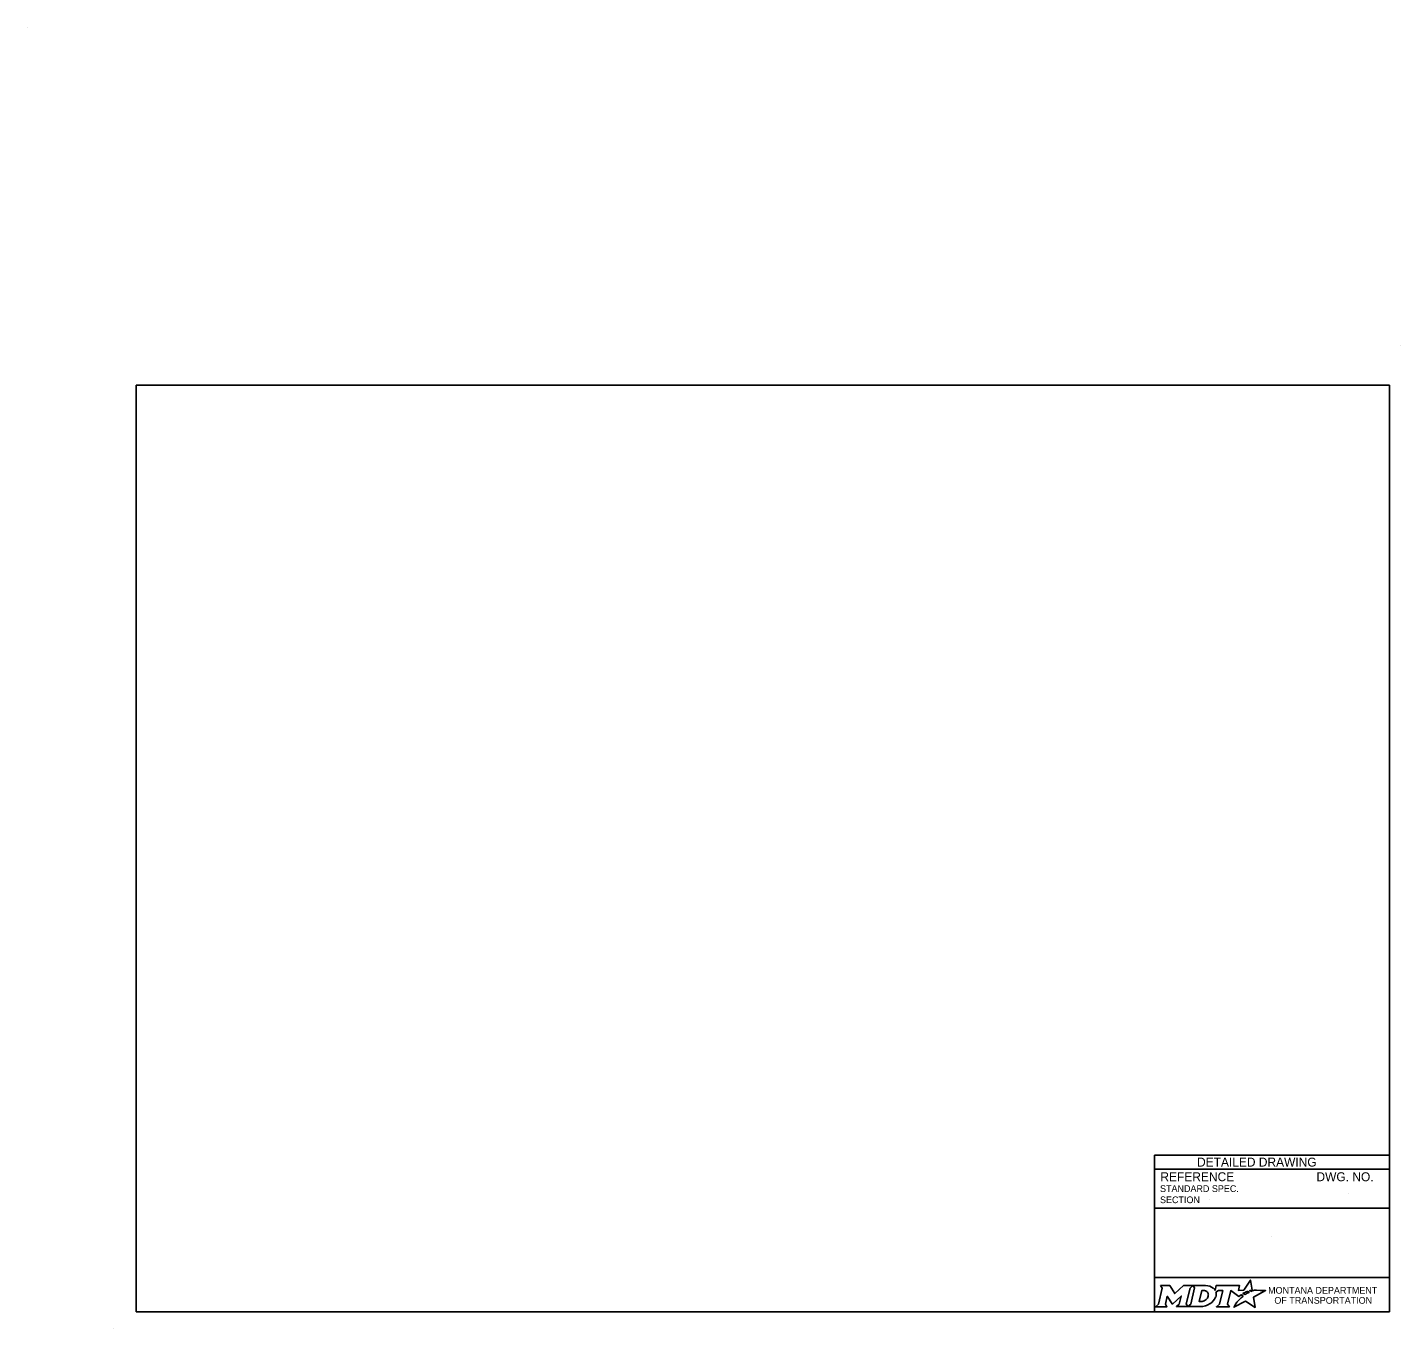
# Model space of a CAD drawing. Extents: x 49991.4 to 50021, y 49987.6 to 50011.4.
# Drawn here: x 50008.76 to 50021.04, y 49999.74 to 50011.36 of the extents above; entities that cross this region are included whole.
import ezdxf

# ---------------------------------------------------------------- set-up
doc = ezdxf.new("R2010")
doc.units = 0
for name, color, linetype in [('Default', 7, 'Continuous'), ('Level 1', 7, 'Continuous'), ('Level 4', 7, 'Continuous')]:
    doc.layers.add(name, color=color, linetype=linetype)

msp = doc.modelspace()

# ---------------------------------------------------------------- linework, layer by layer
at = {"layer": 'Default'}
for points in [[(50018.893, 50000.121), (50018.907, 50000.097), (50018.874, 49999.954), (50018.848, 49999.931), (50018.95, 49999.931), (50018.936, 49999.954), (50018.952, 50000.024), (50018.996, 49999.955), (50019.002, 49999.955), (50019.077, 50000.025), (50019.06, 49999.954), (50019.035, 49999.932), (50019.137, 49999.932), (50019.123, 49999.955), (50019.156, 50000.097)], [(50019.156, 50000.097), (50019.182, 50000.121), (50019.099, 50000.121), (50019.02, 50000.048), (50018.975, 50000.12), (50018.893, 50000.121)], [(50019.295, 50000.121), (50019.182, 50000.121), (50019.196, 50000.098), (50019.163, 49999.954), (50019.137, 49999.932), (50019.248, 49999.932)], [(50019.7, 50000.068), (50019.69, 50000.074), (50019.702, 50000.076), (50019.713, 50000.078), (50019.696, 50000.168), (50019.636, 50000.077), (50019.589, 50000.076), (50019.599, 50000.12), (50019.39, 50000.121), (50019.38, 50000.078), (50019.374, 50000.086)], [(50019.319, 50000.034), (50019.318, 50000.026), (50019.315, 50000.017), (50019.311, 50000.008), (50019.305, 50000.001), (50019.299, 49999.994), (50019.291, 49999.988), (50019.282, 49999.983), (50019.273, 49999.979), (50019.264, 49999.977), (50019.255, 49999.976), (50019.239, 49999.976), (50019.263, 50000.076), (50019.279, 50000.076), (50019.286, 50000.075), (50019.294, 50000.073), (50019.301, 50000.07), (50019.307, 50000.066), (50019.311, 50000.061), (50019.315, 50000.055), (50019.318, 50000.049), (50019.319, 50000.042), (50019.32, 50000.038), (50019.319, 50000.034)], [(50019.387, 50000.062), (50019.411, 50000.075), (50019.448, 50000.075), (50019.42, 49999.954), (50019.392, 49999.931), (50019.508, 49999.931), (50019.491, 49999.954), (50019.52, 50000.075), (50019.591, 50000.023), (50019.612, 50000.038), (50019.632, 50000.027)], [(50019.576, 49999.971), (50019.561, 49999.947), (50019.556, 49999.939), (50019.55, 49999.931), (50019.548, 49999.926), (50019.653, 49999.979), (50019.737, 49999.924), (50019.724, 50000.017), (50019.831, 50000.075), (50019.782, 50000.076), (50019.751, 50000.077), (50019.731, 50000.077), (50019.724, 50000.075), (50019.719, 50000.074), (50019.711, 50000.072), (50019.7, 50000.068)], [(50019.59, 49999.987), (50019.59, 49999.987)], [(50019.65, 50000.04), (50019.648, 50000.039), (50019.629, 50000.048), (50019.639, 50000.054), (50019.644, 50000.056), (50019.652, 50000.06), (50019.658, 50000.063), (50019.666, 50000.066), (50019.673, 50000.068), (50019.685, 50000.061), (50019.681, 50000.059), (50019.676, 50000.056), (50019.672, 50000.054), (50019.667, 50000.051), (50019.665, 50000.05), (50019.662, 50000.049), (50019.66, 50000.047), (50019.658, 50000.046), (50019.655, 50000.044), (50019.652, 50000.042), (50019.65, 50000.04)], [(50019.293, 49999.939), (50019.302, 49999.942), (50019.315, 49999.947), (50019.335, 49999.958)]]:
    msp.add_lwpolyline(points, dxfattribs=at)
for centre, radius, start, end in [((50019.274, 50000.059), 0.118, 300.9103, 339.1383), ((50019.319, 50000.042), 0.0709, 339.5329, 15.8582)]:
    msp.add_arc(centre, radius, start, end, dxfattribs=at)
for centre, major_axis, ratio, start_param, end_param in [((50019.293, 50000.073), (0.0834, -0.0037), 0.568097, 0.61298, 1.570796), ((50019.349, 50000.081), (0.0361, -0.0295), 0.469099, 1.225588, 1.570796), ((50019.583, 49999.979), (-0.00694, -0.00806), 0.008222, 0, 3.137361), ((50019.6, 49999.997), (-0.0098, -0.0102), 0.016458, 3.141593, 6.279097), ((50019.621, 50000.017), (-0.0112, -0.0097), 0.021651, 3.157348, 6.283185), ((50019.248, 50000.08), (0, 0.148), 0.987302, 3.139398, 3.456847)]:
    msp.add_ellipse(centre, major_axis=major_axis, ratio=ratio, start_param=start_param, end_param=end_param, dxfattribs=at)
at = {"layer": 'Level 1'}
for p, q in [((50008.765, 50011.363), (50008.765, 50011.363)), ((50021.038, 50008.524), (50021.038, 50008.524)), ((50009.537, 49999.736), (50009.537, 49999.736))]:
    msp.add_line(p, q, dxfattribs=at)
msp.add_lwpolyline([(50020.938, 50008.165), (50009.737, 50008.165), (50009.737, 49999.886), (50020.938, 49999.886)], close=True, dxfattribs=at)
at = {"layer": 'Level 4'}
for p, q in [((50020.938, 50001.286), (50018.838, 50001.286)), ((50018.838, 50001.286), (50018.838, 49999.886)), ((50020.938, 50001.161), (50018.838, 50001.161)), ((50019.332, 50000.886), (50019.332, 50000.886)), ((50020.574, 50000.946), (50020.574, 50000.946)), ((50020.938, 50000.811), (50018.838, 50000.811)), ((50019.888, 50000.562), (50019.888, 50000.562)), ((50020.938, 50000.193), (50018.838, 50000.193))]:
    msp.add_line(p, q, dxfattribs=at)

# ---------------------------------------------------------------- texts
at = {"layer": 'Default'}
for s, p in [('MONTANA DEPARTMENT', (50019.854, 50000.047)), ('OF TRANSPORTATION', (50019.91, 49999.957))]:
    msp.add_text(s, height=0.06, dxfattribs=at).set_placement(p)
at = {"layer": 'Level 4'}
for s, height, p in [('DETAILED DRAWING', 0.0799, (50019.219, 50001.183)), ('REFERENCE', 0.08, (50018.891, 50001.052)), ('DWG. NO.', 0.08, (50020.286, 50001.052)), ('STANDARD SPEC.', 0.06, (50018.888, 50000.956)), ('SECTION', 0.06, (50018.888, 50000.856))]:
    msp.add_text(s, height=height, dxfattribs=at).set_placement(p)

doc.saveas('drawing.dxf')
